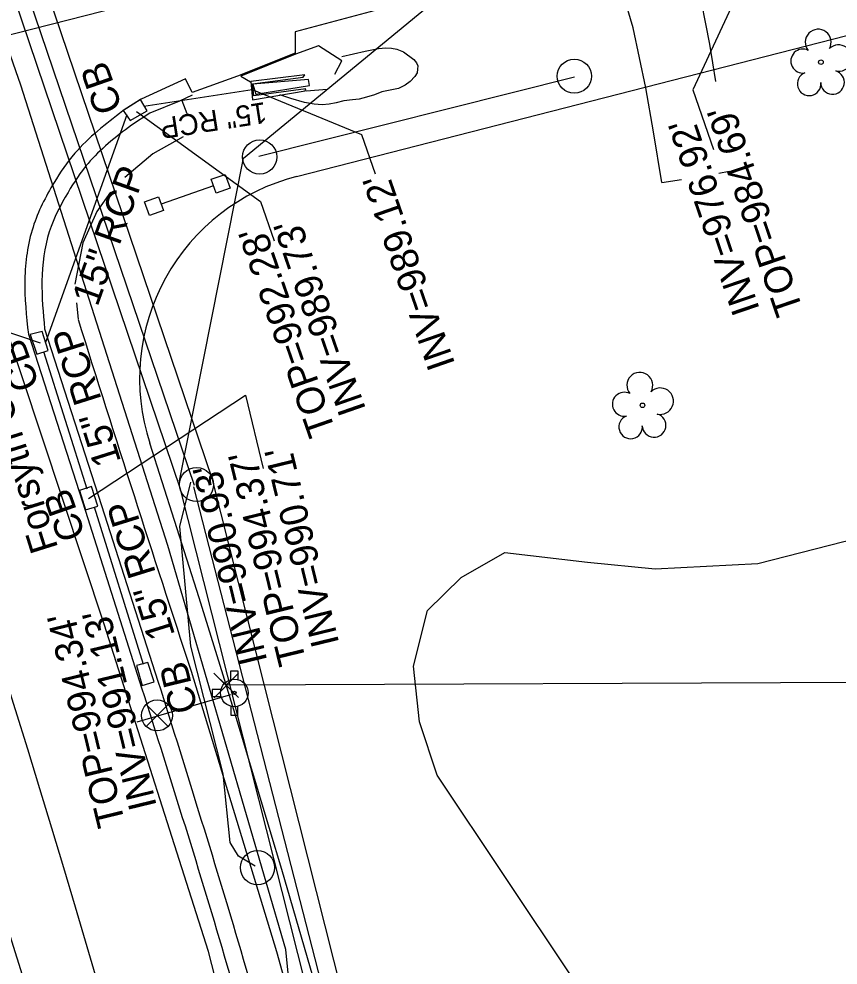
# Model space of a CAD drawing. Extents: x 1614427 to 1617186, y 896524 to 905462.
# Drawn here: x 1616589.9 to 1616707.7, y 902851.6 to 902987.6 of the extents above; entities that cross this region are included whole.
import ezdxf

# ---------------------------------------------------------------- set-up
doc = ezdxf.new("R2010")
doc.units = 0
for name, color, linetype in [('Exist Building', 7, 'Continuous'), ('Exist Horizontal Alignment', 7, 'Continuous'), ('Exist Other Culture Area Outline', 7, 'Continuous'), ('Exist Other Culture Sign', 7, 'Continuous'), ('Exist Property Corner CELL', 7, 'Continuous'), ('Exist Property Line', 7, 'Continuous'), ('Exist Right of Way Line', 7, 'Continuous'), ('Exist Roads Curbs', 7, 'Continuous'), ('Exist Roads EOP', 7, 'Continuous'), ('Exist Roads EOP Other', 7, 'Continuous'), ('Exist Roads EOT', 7, 'Continuous'), ('Exist Structure Minor Catch Basin', 7, 'Continuous'), ('Exist Structure Minor Catch Basin Leader', 7, 'Continuous'), ('Exist Structure Minor Catch Basin Text', 7, 'Continuous'), ('Exist Structure Minor Catch Basin Top Elevation', 7, 'Continuous'), ('Exist Structure Minor Head and End Wall', 7, 'Continuous'), ('Exist Structure Minor Paved Ditch or Gutter', 7, 'Continuous'), ('Exist Structure Minor Pipes RCP 15 Inch', 7, 'Continuous'), ('Exist Structure Minor Pipes RCP 15 Inch Invert', 7, 'Continuous'), ('Exist Structure Minor Pipes RCP 15 Inch Leader', 7, 'Continuous'), ('Exist Structure Minor Pipes RCP 15 Inch Text', 7, 'Continuous'), ('Exist Utilities Other Pole CELL', 7, 'Continuous'), ('Exist Utilities Power UG Cable SUE LOS B', 7, 'Continuous'), ('Exist Utilities Power UG Cable SUE LOS D', 7, 'Continuous'), ('Exist Utilities Sanitary Sewer Manhole Leader', 7, 'Continuous'), ('Exist Utilities Sanitary Sewer Manhole Text', 7, 'Continuous'), ('Exist Utilities Sanitary Sewer UG Line Invert Elevation', 7, 'Continuous'), ('Exist Utilities Telephone UG Cable SUE LOS B', 7, 'Continuous'), ('Exist Utilities Telephone UG FO SUE LOS B', 7, 'Continuous'), ('Exist Utilities Telephone UG FO SUE LOS D', 7, 'Continuous'), ('Exist Utilities TV UG FO Cable SUE LOS D', 7, 'Continuous'), ('Exist Utilities Water Fire Hydrant CELL', 7, 'Continuous'), ('Exist Utilities Water UG Line SUE LOS B', 7, 'Continuous'), ('Exist Utilities Water UG Line SUE LOS B Text', 7, 'Continuous'), ('Exist Utilities Water Valve CELL', 7, 'Continuous'), ('Exist Vegetation Tree CELL', 7, 'Continuous'), ('Exist Vegetation Woods Line', 7, 'Continuous')]:
    doc.layers.add(name, color=color, linetype=linetype)

# ---------------------------------------------------------------- blocks, each defined once
blk = doc.blocks.new('EXIST UTILITIES WATER FIRE HYDRANT')
at = {"layer": 'Exist Utilities Water Fire Hydrant CELL'}
blk.add_line((0, 0), (0, 0), dxfattribs=at)
for points in [[(-0.01025, 0.03825), (-0.01025, 0.064), (0.01025, 0.064), (0.01025, 0.03775)], [(-0.03825, 0.01025), (-0.064, 0.01025), (-0.064, -0.01025), (-0.03825, -0.01025)], [(-0.01025, -0.03825), (-0.01025, -0.064), (0.01025, -0.064), (0.01025, -0.03775)]]:
    blk.add_lwpolyline(points, dxfattribs=at)
for radius in [0.03954, 0.00485]:
    blk.add_circle((0, 0), radius, dxfattribs=at)
blk = doc.blocks.new('EXIST UTILITIES WATER VALVE')
at = {"layer": 'Exist Utilities Water Valve CELL'}
blk.add_lwpolyline([(0.0315, 0.0315), (-0.0315, -0.0315), (0, 0), (0.0315, -0.0315), (-0.0315, 0.0315)], dxfattribs=at)
blk.add_circle((0, 0), 0.0445, dxfattribs=at)

msp = doc.modelspace()

# ---------------------------------------------------------------- linework, layer by layer
at = {"layer": 'Exist Building'}
for points in [[(1616618.26, 902962.6), (1616617.56, 902964.58), (1616619.58, 902965.29), (1616620.27, 902963.31)], [(1616608.66, 902959.37), (1616607.97, 902961.36), (1616609.98, 902962.06), (1616610.68, 902960.08)]]:
    msp.add_lwpolyline(points, close=True, dxfattribs=at)
at = {"layer": 'Exist Horizontal Alignment'}
msp.add_line((1616559.36, 902977.88), (1616875.77, 903058.99), dxfattribs=at)
msp.add_arc((1614325.74, 902186.35), 2370, 9.05, 18.23333, dxfattribs=at)
at = {"layer": 'Exist Other Culture Area Outline'}
msp.add_lwpolyline([(1616636.33, 902982.26), (1616639.69, 902983), (1616641.6, 902983.37), (1616642.69, 902983.51), (1616643.5, 902983.45), (1616644.27, 902983.32), (1616645.23, 902982.9), (1616646.68, 902981.83), (1616647.09, 902981.34), (1616647.26, 902980.91), (1616647.25, 902980.41), (1616647.16, 902979.91), (1616646.84, 902979.35), (1616646.16, 902978.65), (1616645.46, 902978.13), (1616644.51, 902977.64), (1616643.29, 902977.38), (1616642.1, 902977.16), (1616641.06, 902976.73), (1616639.89, 902976.39), (1616638.86, 902976.1), (1616637.9, 902976.03), (1616636.61, 902975.89), (1616635.52, 902975.6), (1616634.5, 902975.38), (1616633.51, 902975.28), (1616632.34, 902975.39), (1616630.99, 902975.64), (1616628.99, 902976.18), (1616627.41, 902976.73)], dxfattribs=at)
at = {"layer": 'Exist Other Culture Sign'}
msp.add_lwpolyline([(1616617.9, 902963.62), (1616610.34, 902961.03)], dxfattribs=at)
at = {"layer": 'Exist Property Corner CELL'}
msp.add_line((1616619.71, 902891.82), (1616619.71, 902891.82), dxfattribs=at)
msp.add_lwpolyline([(1616617.95, 902890.04), (1616621.47, 902893.59), (1616619.71, 902891.82), (1616617.94, 902893.58), (1616621.49, 902890.06)], dxfattribs=at)
at = {"layer": 'Exist Property Line'}
msp.add_line((1616848.57, 902892.86), (1616619.71, 902891.82), dxfattribs=at)
at = {"layer": 'Exist Right of Way Line'}
msp.add_line((1616629.8, 902964.97), (1616864.56, 903025.15), dxfattribs=at)
for centre, radius, start, end in [((1616637.25, 902935.91), 30, 104.3776, 197.9664), ((1614325.74, 902186.35), 2400, 9.05, 17.96643), ((1614325.74, 902186.35), 2340, 9.05, 18.2273)]:
    msp.add_arc(centre, radius, start, end, dxfattribs=at)
at = {"layer": 'Exist Roads Curbs'}
for p, q in [((1616593.57, 902943.06), (1616601.76, 902917.68)), ((1616601.76, 902917.68), (1616609.89, 902892.41))]:
    msp.add_line(p, q, dxfattribs=at)
msp.add_lwpolyline([(1616614.8, 902976.7), (1616613, 902975.82), (1616608.73, 902974.09), (1616606.08, 902972.36)], dxfattribs=at)
for points in [[(1616606.08, 902972.36), (1616602.71, 902969.71), (1616599.82, 902966.85), (1616596.95, 902962.7), (1616594.25, 902957.05), (1616593.19, 902949.97), (1616593.57, 902943.06)], [(1616609.89, 902892.41), (1616622.17, 902852.43), (1616633.45, 902811.75), (1616643.74, 902771.73), (1616653.39, 902730.67), (1616662.94, 902688.03), (1616671.61, 902645.14)]]:
    msp.add_spline(points, degree=3, dxfattribs=at)
at = {"layer": 'Exist Roads EOP'}
for p, q in [((1616591.24, 902942.3), (1616599.45, 902916.85)), ((1616599.45, 902916.85), (1616607.54, 902891.47))]:
    msp.add_line(p, q, dxfattribs=at)
msp.add_lwpolyline([(1616878.19, 903049.82), (1616855.26, 903044.23), (1616818.13, 903035.07), (1616779.6, 903025.26), (1616742.15, 903015.54), (1616704.13, 903005.71), (1616666.3, 902995.63), (1616629.65, 902985.77), (1616629.63, 902982.73), (1616621.35, 902979.4), (1616614.83, 902977.07), (1616613.84, 902979.02), (1616607.46, 902976.12), (1616604.83, 902974.41)], dxfattribs=at)
for points in [[(1616664.02, 902435.24), (1616659.23, 902479.02), (1616653.86, 902521.19), (1616647.48, 902561.19), (1616640.05, 902603.13), (1616633.52, 902638.17), (1616624.95, 902680.56), (1616615.82, 902721.84), (1616606.01, 902763.05), (1616595.75, 902801.7), (1616584.26, 902841.93), (1616572.3, 902881.24), (1616564.26, 902906.37), (1616556.43, 902931.12), (1616543.99, 902967.9), (1616530.08, 903008.97), (1616517.05, 903047.39)], [(1616604.83, 902974.41), (1616601.19, 902971.52), (1616597.92, 902968.32), (1616594.94, 902964.11), (1616591.91, 902957.72), (1616590.73, 902950.15), (1616591.24, 902942.3)], [(1616607.54, 902891.47), (1616619.8, 902851.65), (1616630.95, 902811.11), (1616641.26, 902771.18), (1616651.06, 902730.14), (1616660.51, 902687.43), (1616669.23, 902644.79), (1616673.27, 902623.83), (1616676.02, 902609.12), (1616683.43, 902567.11), (1616690.02, 902525.73), (1616695.57, 902482.82), (1616700.47, 902437.88)]]:
    msp.add_spline(points, degree=3, dxfattribs=at)
at = {"layer": 'Exist Roads EOP Other'}
for points in [[(1616690.14, 902978.63), (1616689.28, 902984), (1616687.51, 902993.09)], [(1616682.4, 902964.13), (1616681.18, 902971.42), (1616680.07, 902977.73), (1616678.24, 902986.35), (1616676.89, 902991.09)], [(1616623.52, 902978.24), (1616623.99, 902976.83), (1616631.71, 902978.06), (1616631.55, 902978.95), (1616623.52, 902978.24)], [(1616613.33, 902975.91), (1616614.04, 902974.05)], [(1616613.51, 902970.67), (1616609.17, 902968.25), (1616605.12, 902964.84)], [(1616690.61, 902965.47), (1616692.08, 902965.76)], [(1616682.4, 902964.13), (1616685.24, 902964.54)], [(1616603.08, 902962.71), (1616601.1, 902959.97), (1616599.07, 902955.43), (1616597.93, 902949.5)], [(1616598.18, 902946.82), (1616598.39, 902944.45)], [(1616614.65, 902893.86), (1616626.96, 902853.56), (1616638.24, 902812.83), (1616648.55, 902772.75), (1616658.26, 902731.61), (1616667.73, 902688.88), (1616676.31, 902647.23)]]:
    msp.add_lwpolyline(points, dxfattribs=at)
msp.add_ellipse((1620606.65, 904204.25), major_axis=(1296.88, -4007.82), ratio=0.997424, start_param=4.703983, end_param=4.716597, dxfattribs=at)
at = {"layer": 'Exist Roads EOT'}
msp.add_spline([(1616665.13, 902435.43), (1616660.48, 902479.08), (1616654.89, 902521.26), (1616648.51, 902561.33), (1616641.12, 902603.28), (1616634.46, 902638.28), (1616625.9, 902680.69), (1616616.67, 902721.99), (1616606.86, 902763.22), (1616596.71, 902801.99), (1616585.45, 902842.18), (1616573.19, 902881.5), (1616565.19, 902906.61), (1616557.25, 902931.31), (1616544.89, 902968.22), (1616530.94, 903009.35), (1616518.06, 903047.65)], degree=3, dxfattribs=at)
at = {"layer": 'Exist Structure Minor Catch Basin'}
for points in [[(1616608.35, 902974.45), (1616607.39, 902976.05), (1616604.9, 902974.48), (1616605.9, 902973.04), (1616608.35, 902974.45)], [(1616593.24, 902942.71), (1616591.52, 902942.25), (1616592.46, 902939.42), (1616594.08, 902939.98), (1616593.24, 902942.71)], [(1616600.34, 902920.41), (1616598.59, 902919.81), (1616599.46, 902917.04), (1616601.22, 902917.6), (1616600.34, 902920.41)], [(1616608.45, 902895.12), (1616606.81, 902894.66), (1616607.59, 902891.81), (1616609.32, 902892.32), (1616608.45, 902895.12)]]:
    msp.add_lwpolyline(points, dxfattribs=at)
at = {"layer": 'Exist Structure Minor Catch Basin Leader'}
for points in [[(1616606.8, 902974.35), (1616624.63, 902961.4), (1616626.6, 902955.73)], [(1616592.99, 902941.03), (1616583.17, 902944.35), (1616581.19, 902950.02)], [(1616599.91, 902918.7), (1616622.48, 902933.53), (1616625.03, 902922.99)]]:
    msp.add_lwpolyline(points, dxfattribs=at)
at = {"layer": 'Exist Structure Minor Head and End Wall'}
msp.add_lwpolyline([(1616631.02, 902979.59), (1616623.24, 902978.64), (1616623.51, 902976), (1616631.07, 902977.31), (1616631.16, 902977.6), (1616623.66, 902976.59), (1616623.47, 902978.3), (1616630.8, 902979.28), (1616631.02, 902979.59)], dxfattribs=at)
at = {"layer": 'Exist Structure Minor Paved Ditch or Gutter'}
msp.add_line((1616631.21, 902977.32), (1616634.22, 902977.55), dxfattribs=at)
msp.add_lwpolyline([(1616635.36, 902979.69), (1616636.34, 902981.62), (1616633, 902983.78), (1616629.69, 902982.59), (1616621.83, 902979.43), (1616623.19, 902978.61)], dxfattribs=at)
at = {"layer": 'Exist Structure Minor Pipes RCP 15 Inch'}
for p, q in [((1616607.86, 902975.08), (1616623.44, 902977.52)), ((1616607.86, 902975.08), (1616623.44, 902977.52)), ((1616605.42, 902973.84), (1616593.71, 902941.12)), ((1616605.42, 902973.84), (1616593.71, 902941.12)), ((1616593.43, 902939.83), (1616599.67, 902920.09)), ((1616593.43, 902939.83), (1616599.67, 902920.09)), ((1616600.73, 902917.48), (1616607.74, 902894.88)), ((1616600.73, 902917.48), (1616607.74, 902894.88))]:
    msp.add_line(p, q, dxfattribs=at)
at = {"layer": 'Exist Structure Minor Pipes RCP 15 Inch Leader'}
msp.add_lwpolyline([(1616623.44, 902977.52), (1616639.18, 902971.04), (1616641.15, 902965.37)], dxfattribs=at)
at = {"layer": 'Exist Utilities Other Pole CELL'}
for centre in [(1616669.79, 902979.41), (1616624.52, 902967.8), (1616615.44, 902920.69), (1616624.21, 902865.6)]:
    msp.add_circle(centre, 2.46, dxfattribs=at)
at = {"layer": 'Exist Utilities Power UG Cable SUE LOS B'}
msp.add_lwpolyline([(1616623.85, 902865.82), (1616621.48, 902867.23), (1616620.29, 902869.23), (1616619.26, 902879.11), (1616614.62, 902897.44), (1616613.01, 902914.67), (1616614.62, 902921.01)], dxfattribs=at)
at = {"layer": 'Exist Utilities Power UG Cable SUE LOS D'}
for p, q in [((1616622.19, 902967.64), (1616769.1, 903088.48)), ((1616624.41, 902967.92), (1616669.82, 902979.31)), ((1616612.97, 902921.22), (1616622.19, 902967.64))]:
    msp.add_line(p, q, dxfattribs=at)
for points in [[(1616613.11, 902920.04), (1616557.62, 903083.85), (1616506.31, 903236.48), (1616432.49, 903448.81)], [(1616729.53, 902223.32), (1616715.76, 902408.53), (1616690.86, 902610.12), (1616647.98, 902782.13), (1616613.11, 902920.04)]]:
    msp.add_lwpolyline(points, dxfattribs=at)
at = {"layer": 'Exist Utilities Sanitary Sewer Manhole Leader'}
msp.add_lwpolyline([(1616697.24, 902999.83), (1616686.84, 902977.46), (1616689.8, 902968.87)], dxfattribs=at)
at = {"layer": 'Exist Utilities Telephone UG Cable SUE LOS B'}
msp.add_lwpolyline([(1616653.58, 902416.71), (1616663.67, 902417.14), (1616669.74, 902418.75), (1616672.64, 902421.54), (1616661.03, 902530.35), (1616645.59, 902619.16), (1616624.26, 902721.72), (1616610.21, 902784.31), (1616604.98, 902794.39), (1616600.3, 902799.85), (1616600.03, 902805.22), (1616598.01, 902825.81), (1616571.3, 902910.94), (1616549.08, 902977.64), (1616515.65, 903076.73), (1616483.43, 903168.54), (1616464.03, 903218.81), (1616463.64, 903219.2), (1616462.93, 903219.33), (1616457.94, 903217.72), (1616449, 903216.46)], dxfattribs=at)
at = {"layer": 'Exist Utilities Telephone UG FO SUE LOS B'}
msp.add_lwpolyline([(1616629.3, 902843.73), (1616628.3, 902853.82), (1616611.3, 902911.93), (1616590.16, 902978.12), (1616573.68, 903025.32), (1616565.62, 903043.9), (1616559.79, 903054.5), (1616532.47, 903133.24), (1616521.61, 903168.38), (1616519.36, 903185.77), (1616513.96, 903203.22)], dxfattribs=at)
at = {"layer": 'Exist Utilities Telephone UG FO SUE LOS D'}
msp.add_lwpolyline([(1616734.48, 902223.1), (1616720.44, 902409.02), (1616695.55, 902610.96), (1616652.67, 902783.16), (1616617.73, 902921.41), (1616562.17, 903085.17), (1616510.89, 903237.95), (1616436.43, 903449.85)], dxfattribs=at)
at = {"layer": 'Exist Utilities TV UG FO Cable SUE LOS D'}
for points in [[(1616615.13, 902920.57), (1616559.6, 903084.29), (1616508.29, 903236.97), (1616433.95, 903449.2), (1616409.28, 903583.28), (1616372.35, 903777.82), (1616323.57, 903995.2), (1616266.96, 904282.87), (1616220.39, 904446.95), (1616216.24, 904469.3), (1616198.7, 904563.75), (1616189.79, 904725.95), (1616160.9, 904944.94), (1616137.72, 905120.69)], [(1616742.45, 902033.61), (1616731.67, 902222.81), (1616717.86, 902408.9), (1616693.14, 902610.5), (1616650.43, 902782.74), (1616615.07, 902920.36)]]:
    msp.add_lwpolyline(points, dxfattribs=at)
at = {"layer": 'Exist Utilities Water UG Line SUE LOS B'}
msp.add_line((1616620.34, 902890.47), (1616606.84, 902886.5), dxfattribs=at)
msp.add_lwpolyline([(1616682.85, 901889.35), (1616688.26, 901932.45), (1616696.61, 902016.19), (1616699.26, 902055.42), (1616702.78, 902110.39), (1616705.34, 902181.72), (1616707.31, 902255.35), (1616706.62, 902316.75), (1616703.14, 902377.45), (1616699.12, 902434.84), (1616686.86, 902524.85), (1616669.78, 902622.34), (1616658.13, 902681.62), (1616634.87, 902784.56), (1616617.17, 902853.52), (1616602.15, 902900.61), (1616584.28, 902954.24), (1616571.86, 902993.81)], dxfattribs=at)
msp.add_lwpolyline([(1616682.85, 901889.35), (1616688.26, 901932.45), (1616696.61, 902016.19), (1616699.26, 902055.42), (1616702.78, 902110.39), (1616705.34, 902181.72), (1616707.31, 902255.35), (1616706.62, 902316.75), (1616703.14, 902377.45), (1616699.12, 902434.84), (1616686.86, 902524.85), (1616669.78, 902622.34), (1616658.13, 902681.62), (1616634.87, 902784.56), (1616617.17, 902853.52), (1616602.15, 902900.61), (1616584.28, 902954.24), (1616571.86, 902993.81)], dxfattribs=at)
at = {"layer": 'Exist Vegetation Tree CELL'}
for p, q in [((1616705.28, 902981.42), (1616705.28, 902981.42)), ((1616679.61, 902932.09), (1616679.61, 902932.09))]:
    msp.add_line(p, q, dxfattribs=at)
for centre in [(1616705.28, 902981.42), (1616679.61, 902932.09)]:
    msp.add_circle(centre, 0.326, dxfattribs=at)
for centre, radius, start, end in [((1616704.89, 902984.3), 1.86, 330.1651, 219.7134), ((1616702.67, 902981.58), 1.73, 62.6636, 279.3457), ((1616707.83, 902982.01), 1.9, 257.1011, 134.1999), ((1616703.58, 902978.3), 1.69, 111.5671, 6.231), ((1616706.95, 902978.52), 1.7, 181.2822, 74.56), ((1616679.22, 902934.96), 1.86, 330.1651, 219.7134), ((1616682.16, 902932.68), 1.9, 257.1011, 134.1999), ((1616677, 902932.24), 1.73, 62.6636, 279.3457), ((1616677.9, 902928.97), 1.69, 111.5671, 6.231), ((1616681.28, 902929.19), 1.7, 181.2822, 74.56)]:
    msp.add_arc(centre, radius, start, end, dxfattribs=at)
at = {"layer": 'Exist Vegetation Woods Line'}
msp.add_lwpolyline([(1616668.84, 902764.14), (1616676.13, 902799.8), (1616678.62, 902819.06), (1616675.55, 902835.43), (1616669.55, 902849.77), (1616650.05, 902878.92), (1616647.54, 902886.56), (1616646.67, 902894.57), (1616648.67, 902902.57), (1616653.53, 902907.32), (1616659.81, 902910.93), (1616671.71, 902909.53), (1616681.45, 902908.58), (1616696.21, 902909.36), (1616708.59, 902912.5), (1616716.51, 902914.22), (1616725.21, 902914.81), (1616737.14, 902914.37), (1616745.55, 902915.12), (1616761.84, 902918.71), (1616771.16, 902920.71), (1616780.96, 902922.08), (1616785.68, 902921.01), (1616787.32, 902918.96)], dxfattribs=at)

# ---------------------------------------------------------------- block references
at = {"layer": 'Exist Utilities Water Fire Hydrant CELL', "xscale": 50, "yscale": 50}
msp.add_blockref('EXIST UTILITIES WATER FIRE HYDRANT', (1616620.88, 902890.72), dxfattribs=at)
at = {"layer": 'Exist Utilities Water Valve CELL', "xscale": 50, "yscale": 50}
msp.add_blockref('EXIST UTILITIES WATER VALVE', (1616609.76, 902887.49), dxfattribs=at)

# ---------------------------------------------------------------- texts
at = {"layer": 'Exist Structure Minor Catch Basin Text'}
for rotation, p in [(109.1768, (1616604.82, 902974.8)), (109.1768, (1616592.88, 902934.93)), (109.1768, (1616599.51, 902913.38)), (103.6417, (1616615.66, 902888.3))]:
    msp.add_text('CB', height=4, rotation=rotation, dxfattribs=at).set_placement(p)
at = {"layer": 'Exist Structure Minor Catch Basin Top Elevation'}
for s, rotation, p in [("TOP=992.28'", 109.1768, (1616635.5, 902928.4)), ("TOP=994.37'", 103.6417, (1616631.25, 902895.22)), ("TOP=994.34'", 103.6417, (1616605.19, 902871.98))]:
    msp.add_text(s, height=4, rotation=rotation, dxfattribs=at).set_placement(p)
at = {"layer": 'Exist Structure Minor Pipes RCP 15 Inch Invert'}
for s, rotation, p in [("INV=989.12'", 109.1768, (1616652.68, 902938)), ("INV=989.73'", 109.1768, (1616639.86, 902931.47)), ("INV=990.71'", 103.6417, (1616635.99, 902897.86)), ("INV=990.93'", 103.6417, (1616625.64, 902895.31)), ("INV=991.13'", 103.6417, (1616609.74, 902874.43))]:
    msp.add_text(s, height=4, rotation=rotation, dxfattribs=at).set_placement(p)
at = {"layer": 'Exist Structure Minor Pipes RCP 15 Inch Text'}
for height, rotation, p in [(3, 188.8757, (1616625.28, 902975.71)), (4, 70.2973, (1616601.18, 902946.15)), (4, 107.5429, (1616604.62, 902924.01)), (4, 107.232, (1616612.38, 902899.07))]:
    msp.add_text('15" RCP', height=height, rotation=rotation, dxfattribs=at).set_placement(p)
at = {"layer": 'Exist Utilities Sanitary Sewer Manhole Text'}
msp.add_text("TOP=984.69'", height=4, rotation=108.8416, dxfattribs=at).set_placement((1616702.76, 902945.76))
at = {"layer": 'Exist Utilities Sanitary Sewer UG Line Invert Elevation'}
msp.add_text("INV=976.92'", height=4, rotation=108.8416, dxfattribs=at).set_placement((1616696.51, 902945.87))
at = {"layer": 'Exist Utilities Water UG Line SUE LOS B Text'}
msp.add_text('Forsyth County Water & Sewer', height=4, rotation=107.42, dxfattribs=at).set_placement((1616595.56, 902911.59))

doc.saveas('drawing.dxf')
